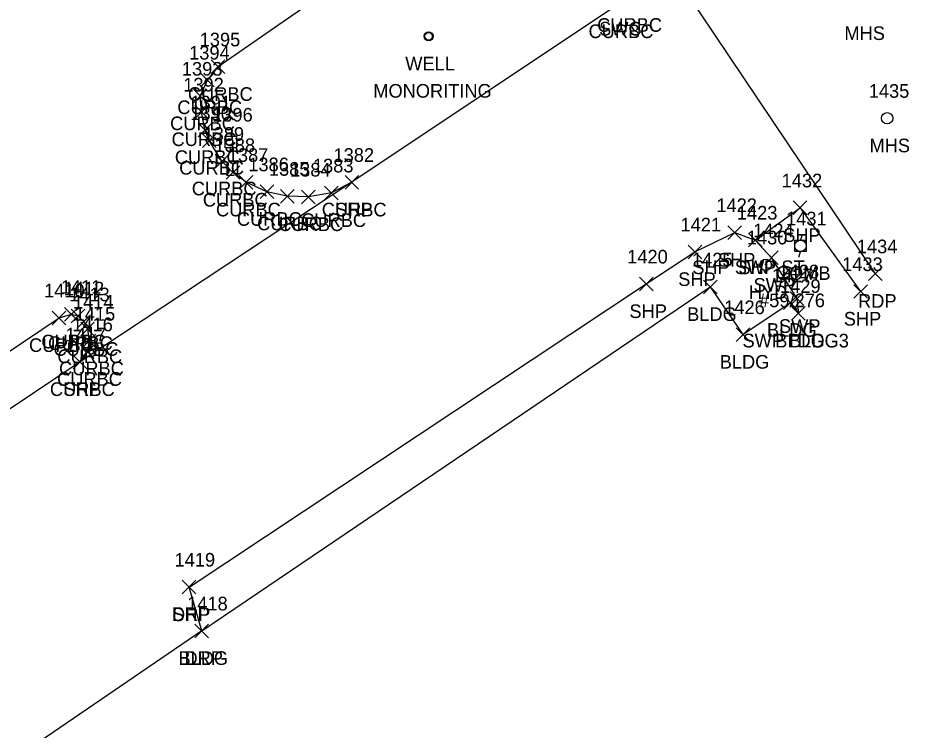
# Model space of a CAD drawing. Extents: x 1635588 to 1637550, y 621583 to 623638.
# Drawn here: x 1636890.8 to 1637021.6, y 622165 to 622269.5 of the extents above; entities that cross this region are included whole.
import ezdxf

# ---------------------------------------------------------------- set-up
doc = ezdxf.new("R2010")
doc.units = 0
for name, color, linetype in [('L_A', 7, 'Continuous'), ('L_I', 7, 'Continuous'), ('L_TIC', 7, 'Continuous'), ('LBC', 7, 'Continuous'), ('P_A', 7, 'Continuous'), ('P_I', 7, 'Continuous'), ('P_TIC', 7, 'Continuous'), ('PET', 7, 'Continuous'), ('PSP', 7, 'Continuous'), ('R_A', 7, 'Continuous'), ('R_I', 7, 'Continuous'), ('R_TIC', 7, 'Continuous'), ('RC', 7, 'Continuous'), ('RDP', 7, 'Continuous'), ('RSW', 7, 'Continuous'), ('U_A', 7, 'Continuous'), ('U_C', 7, 'Continuous'), ('U_I', 7, 'Continuous'), ('ULP', 7, 'Continuous'), ('UP', 7, 'Continuous'), ('USMH', 7, 'Continuous'), ('UWFH', 7, 'Continuous'), ('UWW', 7, 'Continuous')]:
    doc.layers.add(name, color=color, linetype=linetype)

msp = doc.modelspace()

# ---------------------------------------------------------------- linework, layer by layer
at = {"layer": 'L_TIC'}
for points in [[(1636991.43, 622229.06), (1636993.43, 622231.06)], [(1636993.43, 622229.06), (1636991.43, 622231.06)], [(1637003.16, 622226.74), (1637005.16, 622228.74)], [(1637005.16, 622226.74), (1637003.16, 622228.74)], [(1637004.37, 622225.17), (1637006.37, 622227.17)], [(1637006.37, 622225.17), (1637004.37, 622227.17)], [(1636996.22, 622222.06), (1636998.22, 622224.06)], [(1636998.22, 622222.06), (1636996.22, 622224.06)], [(1636916.78, 622178.59), (1636918.78, 622180.59)], [(1636918.78, 622178.59), (1636916.78, 622180.59)], [(1636916.78, 622178.59), (1636918.78, 622180.59)], [(1636918.78, 622178.59), (1636916.78, 622180.59)]]:
    msp.add_lwpolyline(points, dxfattribs=at)
at = {"layer": 'LBC'}
for points in [[(1636917.78, 622179.59), (1636992.43, 622230.06), (1636997.22, 622223.06), (1637004.16, 622227.74), (1637005.37, 622226.17)], [(1636917.78, 622179.59), (1636857.25, 622138.25), (1636873.71, 622114.67)]]:
    msp.add_lwpolyline(points, dxfattribs=at)
at = {"layer": 'P_TIC'}
for points in [[(1636938.82, 622244.4), (1636940.82, 622246.4)], [(1636940.82, 622244.4), (1636938.82, 622246.4)], [(1637004.6, 622240.66), (1637006.6, 622242.66)], [(1637006.6, 622240.66), (1637004.6, 622242.66)], [(1636995.01, 622237.03), (1636997.01, 622239.03)], [(1636997.01, 622237.03), (1636995.01, 622239.03)], [(1636998.02, 622235.93), (1637000.02, 622237.93)], [(1637000.02, 622235.93), (1636998.02, 622237.93)], [(1636989.18, 622234.19), (1636991.18, 622236.19)], [(1636991.18, 622234.19), (1636989.18, 622236.19)], [(1637015.63, 622230.99), (1637017.63, 622232.99)], [(1637017.63, 622230.99), (1637015.63, 622232.99)], [(1636982.02, 622229.49), (1636984.02, 622231.49)], [(1636984.02, 622229.49), (1636982.02, 622231.49)], [(1637013.48, 622228.38), (1637015.48, 622230.38)], [(1637015.48, 622228.38), (1637013.48, 622230.38)], [(1636898.93, 622218.05), (1636900.93, 622220.05)], [(1636900.93, 622218.05), (1636898.93, 622220.05)], [(1636914.93, 622185.02), (1636916.93, 622187.02)], [(1636916.93, 622185.02), (1636914.93, 622187.02)]]:
    msp.add_lwpolyline(points, dxfattribs=at)
at = {"layer": 'PET'}
msp.add_lwpolyline([(1636496.54, 623045.3), (1636533.69, 622970.65), (1636546.95, 622944.69), (1636557.06, 622926.23), (1636579, 622887.89), (1636603.72, 622849.48), (1636616.07, 622830.82), (1636647.79, 622783.76), (1636703.25, 622700.68), (1636737.08, 622649.81), (1636763.83, 622609.67), (1636812.95, 622535.62), (1636858.06, 622468.21), (1636878.24, 622438.26), (1636911.18, 622389.38), (1636974.88, 622293.33), (1636986.61, 622276.7), (1637016.63, 622231.99)], dxfattribs=at)
at = {"layer": 'PSP'}
for points in [[(1636939.82, 622245.4), (1636899.93, 622219.05)], [(1636915.93, 622186.02), (1636983.02, 622230.49), (1636990.18, 622235.19), (1636996.01, 622238.03), (1636999.02, 622236.93), (1637005.6, 622241.66), (1637014.48, 622229.38)]]:
    msp.add_lwpolyline(points, dxfattribs=at)
at = {"layer": 'R_TIC'}
for points in [[(1636919.18, 622261.35), (1636921.18, 622263.35)], [(1636921.18, 622261.35), (1636919.18, 622263.35)], [(1636919.18, 622261.35), (1636921.18, 622263.35)], [(1636921.18, 622261.35), (1636919.18, 622263.35)], [(1636917.63, 622259.41), (1636919.63, 622261.41)], [(1636919.63, 622259.41), (1636917.63, 622261.41)], [(1636916.56, 622257.05), (1636918.56, 622259.05)], [(1636918.56, 622257.05), (1636916.56, 622259.05)], [(1636916.77, 622254.72), (1636918.77, 622256.72)], [(1636918.77, 622254.72), (1636916.77, 622256.72)], [(1636917.26, 622252.09), (1636919.26, 622254.09)], [(1636919.26, 622252.09), (1636917.26, 622254.09)], [(1636917.9, 622250.53), (1636919.9, 622252.53)], [(1636919.9, 622250.53), (1636917.9, 622252.53)], [(1636919.75, 622247.49), (1636921.75, 622249.49)], [(1636921.75, 622247.49), (1636919.75, 622249.49)], [(1636921.37, 622245.84), (1636923.37, 622247.84)], [(1636923.37, 622245.84), (1636921.37, 622247.84)], [(1636923.3, 622244.4), (1636925.3, 622246.4)], [(1636925.3, 622244.4), (1636923.3, 622246.4)], [(1636938.82, 622244.4), (1636940.82, 622246.4)], [(1636940.82, 622244.4), (1636938.82, 622246.4)], [(1636926.36, 622243.02), (1636928.36, 622245.02)], [(1636928.36, 622243.02), (1636926.36, 622245.02)], [(1636929.33, 622242.36), (1636931.33, 622244.36)], [(1636931.33, 622242.36), (1636929.33, 622244.36)], [(1636935.81, 622242.85), (1636937.81, 622244.85)], [(1636937.81, 622242.85), (1636935.81, 622244.85)], [(1636932.44, 622242.25), (1636934.44, 622244.25)], [(1636934.44, 622242.25), (1636932.44, 622244.25)], [(1636998.02, 622235.93), (1637000.02, 622237.93)], [(1637000.02, 622235.93), (1636998.02, 622237.93)], [(1637000.41, 622233.34), (1637002.41, 622235.34)], [(1637002.41, 622233.34), (1637000.41, 622235.34)], [(1637004.15, 622227.31), (1637006.15, 622229.31)], [(1637006.15, 622227.31), (1637004.15, 622229.31)], [(1636895.86, 622224.51), (1636897.86, 622226.51)], [(1636897.86, 622224.51), (1636895.86, 622226.51)], [(1636897.66, 622225.04), (1636899.66, 622227.04)], [(1636899.66, 622225.04), (1636897.66, 622227.04)], [(1636898.64, 622224.8), (1636900.64, 622226.8)], [(1636900.64, 622224.8), (1636898.64, 622226.8)], [(1637004.37, 622225.17), (1637006.37, 622227.17)], [(1637006.37, 622225.17), (1637004.37, 622227.17)], [(1636899.46, 622223.94), (1636901.46, 622225.94)], [(1636901.46, 622223.94), (1636899.46, 622225.94)], [(1636900.02, 622222.87), (1636902.02, 622224.87)], [(1636902.02, 622222.87), (1636900.02, 622224.87)], [(1636900.26, 622221.1), (1636902.26, 622223.1)], [(1636902.26, 622221.1), (1636900.26, 622223.1)], [(1636899.98, 622219.55), (1636901.98, 622221.55)], [(1636901.98, 622219.55), (1636899.98, 622221.55)], [(1636898.93, 622218.05), (1636900.93, 622220.05)], [(1636900.93, 622218.05), (1636898.93, 622220.05)], [(1636914.93, 622185.02), (1636916.93, 622187.02)], [(1636916.93, 622185.02), (1636914.93, 622187.02)], [(1636916.78, 622178.59), (1636918.78, 622180.59)], [(1636918.78, 622178.59), (1636916.78, 622180.59)]]:
    msp.add_lwpolyline(points, dxfattribs=at)
at = {"layer": 'RC'}
for points in [[(1636904.15, 622393.55), (1636908.09, 622387.62), (1636932.69, 622350.73), (1636948.49, 622327.15), (1636971.86, 622291.81), (1636980.55, 622279.12), (1636981.67, 622276.42), (1636981.49, 622274.59), (1636980.25, 622272.48), (1636978.98, 622271.56), (1636939.82, 622245.4), (1636936.81, 622243.85), (1636933.44, 622243.25), (1636930.33, 622243.36), (1636927.36, 622244.02), (1636924.3, 622245.4), (1636922.37, 622246.84), (1636920.75, 622248.49), (1636918.9, 622251.53), (1636918.26, 622253.09), (1636917.77, 622255.72), (1636917.56, 622258.05), (1636918.63, 622260.41), (1636920.18, 622262.35)], [(1636964.21, 622293.73), (1636961.73, 622294.87), (1636958.74, 622295.48), (1636956.44, 622295.49), (1636954.36, 622294.7), (1636952.06, 622293.27), (1636950.47, 622291.85), (1636949.27, 622290.01), (1636946.74, 622283.33), (1636945.79, 622281.71), (1636943.24, 622278.74), (1636943.04, 622276.05), (1636938.81, 622275.24), (1636920.18, 622262.35)], [(1636847.75, 622192.51), (1636896.86, 622225.51), (1636898.66, 622226.04), (1636899.64, 622225.8), (1636900.46, 622224.94), (1636901.02, 622223.87), (1636901.26, 622222.1), (1636900.98, 622220.55), (1636899.93, 622219.05), (1636865.05, 622195.66), (1636832.89, 622174.21)]]:
    msp.add_lwpolyline(points, dxfattribs=at)
at = {"layer": 'RDP'}
msp.add_lwpolyline([(1636917.78, 622179.59), (1636915.93, 622186.02)], dxfattribs=at)
at = {"layer": 'RSW'}
msp.add_lwpolyline([(1636999.02, 622236.93), (1637001.41, 622234.34), (1637005.15, 622228.31), (1637005.37, 622226.17)], dxfattribs=at)
at = {"layer": 'ULP'}
for p, q in [((1636922.24, 622252.98), (1636922.07, 622252.15)), ((1636921.24, 622250.48), (1636921.24, 622252.15)), ((1636921.24, 622252.15), (1636922.9, 622252.15)), ((1636922.07, 622251.31), (1636922.07, 622251.31)), ((1636922.9, 622252.15), (1636922.9, 622250.48)), ((1636922.9, 622250.48), (1636921.24, 622250.48)), ((1636921.82, 622249.65), (1636922.07, 622250.48))]:
    msp.add_line(p, q, dxfattribs=at)
at = {"layer": 'UP'}
for p, q in [((1637004.84, 622235.24), (1637004.84, 622236.91)), ((1637004.84, 622236.91), (1637006.51, 622236.91)), ((1637005.92, 622237.74), (1637005.67, 622236.91)), ((1637006.51, 622236.91), (1637006.51, 622235.24)), ((1637006.51, 622235.24), (1637004.84, 622235.24)), ((1637005.42, 622234.41), (1637005.67, 622235.24)), ((1637005.67, 622236.08), (1637005.67, 622236.08))]:
    msp.add_line(p, q, dxfattribs=at)
msp.add_circle((1637005.67, 622236.08), 0.833, dxfattribs=at)
at = {"layer": 'USMH'}
for p, q in [((1637018.38, 622254.8), (1637018.38, 622254.8)), ((1637019.21, 622254.8), (1637019.21, 622254.8))]:
    msp.add_line(p, q, dxfattribs=at)
msp.add_circle((1637018.38, 622254.8), 0.833, dxfattribs=at)
at = {"layer": 'UWFH'}
msp.add_line((1637000.57, 622233.29), (1637000.57, 622233.29), dxfattribs=at)
for centre, radius in [((1637000.57, 622233.29), 0.833), ((1636999.57, 622233.29), 0.167), ((1637001.57, 622233.29), 0.167), ((1637000.57, 622232.29), 0.167)]:
    msp.add_circle(centre, radius, dxfattribs=at)
at = {"layer": 'UWW'}
for radius in [0.667, 0.625, 0.583, 0.542]:
    msp.add_circle((1636951.09, 622266.82), radius, dxfattribs=at)

# ---------------------------------------------------------------- texts
at = {"layer": 'L_A'}
for p in [(1636989.03, 622225.06), (1637000.75, 622222.74), (1637001.96, 622221.17), (1636993.81, 622218.06), (1636914.37, 622174.59), (1636914.37, 622174.59)]:
    msp.add_text('BLDG', height=2, dxfattribs=at).set_placement(p)
at = {"layer": 'L_I'}
for s, p in [('1425', (1636989.74, 622233.06)), ('1427', (1637001.47, 622230.74)), ('1429', (1637002.67, 622229.17)), ('1426', (1636994.47, 622226.06)), ('1418', (1636915.65, 622182.59)), ('1418', (1636915.65, 622182.59))]:
    msp.add_text(s, height=2, dxfattribs=at).set_placement(p)
at = {"layer": 'P_A'}
for s, p in [('SHP', (1636937.36, 622240.4)), ('SHP', (1637003.13, 622236.66)), ('SHP', (1636993.54, 622233.03)), ('SHP', (1636996.56, 622231.93)), ('SHP', (1636987.72, 622230.19)), ('RDP', (1637014.12, 622226.99)), ('SHP', (1636980.56, 622225.49)), ('SHP', (1637012.02, 622224.38)), ('SHP', (1636897.47, 622214.05)), ('SHP', (1636913.47, 622181.02))]:
    msp.add_text(s, height=2, dxfattribs=at).set_placement(p)
at = {"layer": 'P_I'}
for s, p in [('1382', (1636937.13, 622248.4)), ('1432', (1637002.9, 622244.66)), ('1422', (1636993.32, 622241.03)), ('1423', (1636996.33, 622239.93)), ('1421', (1636988.06, 622238.19)), ('1434', (1637013.94, 622234.99)), ('1420', (1636980.24, 622233.49)), ('1433', (1637011.79, 622232.38)), ('1417', (1636897.8, 622222.05)), ('1419', (1636913.8, 622189.02))]:
    msp.add_text(s, height=2, dxfattribs=at).set_placement(p)
at = {"layer": 'R_A'}
for s, p in [('CURBC', (1636975.83, 622267.48)), ('CURBC', (1636974.56, 622266.56)), ('SWC', (1636976.11, 622266.94)), ('CURBC', (1636915.76, 622257.35)), ('CURBC', (1636915.76, 622257.35)), ('CURBC', (1636914.21, 622255.41)), ('CURBC', (1636913.15, 622253.05)), ('CURBC', (1636913.36, 622250.72)), ('CURBC', (1636913.84, 622248.09)), ('CURBC', (1636914.48, 622246.53)), ('CURBC', (1636916.33, 622243.49)), ('CURBC', (1636917.95, 622241.84)), ('CURBC', (1636919.88, 622240.4)), ('CURBC', (1636935.41, 622240.4)), ('CURBC', (1636922.95, 622239.02)), ('CURBC', (1636932.39, 622238.85)), ('CURBC', (1636925.92, 622238.36)), ('CURBC', (1636929.03, 622238.25)), ('SHP SWP ST', (1636989.79, 622231.93)), ('SWP', (1636998.78, 622229.34)), ('SWP', (1637002.51, 622223.31)), ('CURBC', (1636892.44, 622220.51)), ('CURBC', (1636894.24, 622221.04)), ('CURBC', (1636895.23, 622220.8)), ('SWP BLDG3', (1636997.16, 622221.17)), ('CURBC', (1636896.04, 622219.94)), ('CURBC', (1636896.6, 622218.87)), ('CURBC', (1636896.85, 622217.1)), ('CURBC', (1636896.56, 622215.55)), ('CURBC', (1636895.51, 622214.05)), ('DRP', (1636913.42, 622181.02)), ('DRP', (1636915.26, 622174.59))]:
    msp.add_text(s, height=2, dxfattribs=at).set_placement(p)
at = {"layer": 'R_I'}
for s, p in [('1395', (1636917.49, 622265.35)), ('1395', (1636917.49, 622265.35)), ('1394', (1636915.94, 622263.41)), ('1393', (1636914.87, 622261.05)), ('1392', (1636915.08, 622258.72)), ('1391', (1636916.13, 622256.09)), ('1390', (1636916.12, 622254.53)), ('1389', (1636918.05, 622251.49)), ('1388', (1636919.67, 622249.84)), ('1387', (1636921.61, 622248.4)), ('1382', (1636937.13, 622248.4)), ('1386', (1636924.62, 622247.02)), ('1385', (1636927.64, 622246.36)), ('1383', (1636934.11, 622246.85)), ('1384', (1636930.75, 622246.25)), ('1423', (1636996.33, 622239.93)), ('1424', (1636998.72, 622237.34)), ('1428', (1637002.45, 622231.31)), ('1410', (1636894.65, 622228.51)), ('1411', (1636897.1, 622229.04)), ('1412', (1636897.52, 622228.8)), ('1413', (1636898.33, 622227.94)), ('1429', (1637002.67, 622229.17)), ('1414', (1636898.89, 622226.87)), ('1415', (1636899.14, 622225.1)), ('1416', (1636898.79, 622223.55)), ('1417', (1636897.8, 622222.05)), ('1419', (1636913.8, 622189.02)), ('1418', (1636915.65, 622182.59))]:
    msp.add_text(s, height=2, dxfattribs=at).set_placement(p)
at = {"layer": 'U_A'}
for s, p in [('MHS', (1637012.12, 622266.28)), ('WELL', (1636947.66, 622261.82)), ('MHS', (1637015.8, 622249.8)), ('LI', (1636921.17, 622246.31)), ('COMB', (1637002.06, 622231.08)), ('HYD', (1636998.09, 622228.29))]:
    msp.add_text(s, height=2, dxfattribs=at).set_placement(p)
at = {"layer": 'U_C'}
for s, p in [('MONORITING', (1636942.97, 622257.82)), ('#59/276', (1636999.59, 622227.08))]:
    msp.add_text(s, height=2, dxfattribs=at).set_placement(p)
at = {"layer": 'U_I'}
for s, p in [('1435', (1637015.69, 622257.8)), ('1396', (1636919.32, 622254.31)), ('1431', (1637003.55, 622239.08)), ('1430', (1636997.79, 622236.29))]:
    msp.add_text(s, height=2, dxfattribs=at).set_placement(p)

doc.saveas('drawing.dxf')
